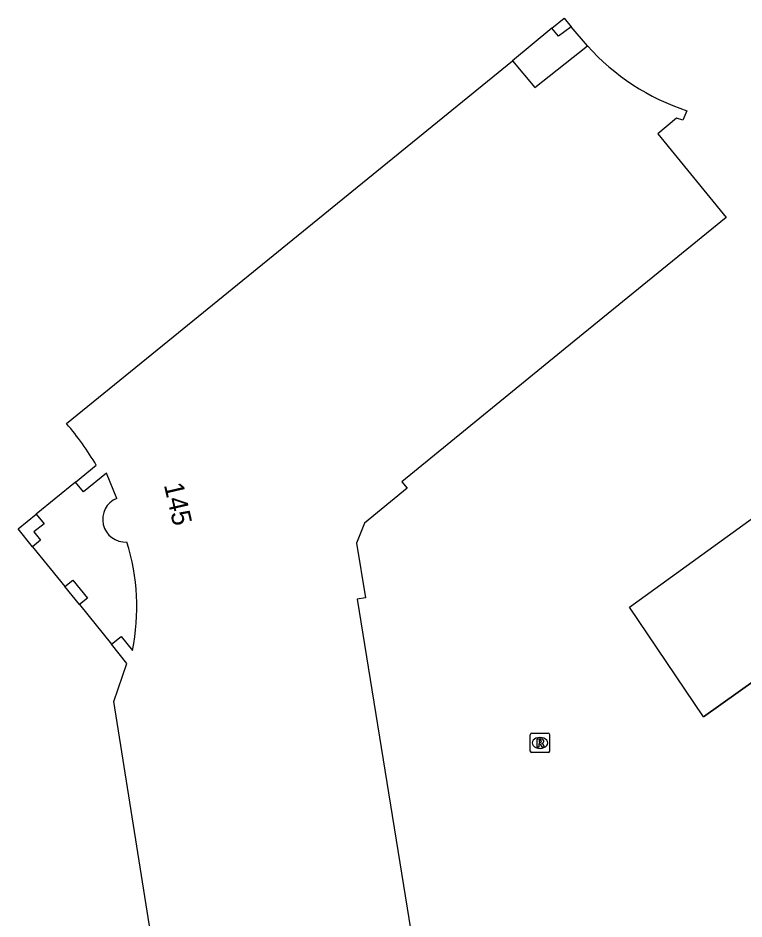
# Model space of a CAD drawing. Extents: x 159265 to 160143, y 383413 to 384319.
# Drawn here: x 159397.74 to 159435.22, y 383470.18 to 383516.69 of the extents above; entities that cross this region are included whole.
import ezdxf

# ---------------------------------------------------------------- set-up
doc = ezdxf.new("R2010")
doc.units = 0
for name, color, linetype in [('IMGEO_Muur', 7, 'Continuous'), ('IMGEO_Pand', 7, 'Continuous'), ('IMGEO_Pand_nummerreeks', 7, 'Continuous'), ('IMGEO_Pand_overbouw', 7, 'Continuous'), ('IMGEO_Rijbaan_lokaal_open', 7, 'Continuous'), ('IMGEO_Rioolput', 7, 'Continuous')]:
    doc.layers.add(name, color=color, linetype=linetype)

msp = doc.modelspace()

# ---------------------------------------------------------------- linework, layer by layer
at = {"layer": 'IMGEO_Muur'}
msp.add_lwpolyline([(159433.127, 383480.612), (159439.516, 383485.157)], dxfattribs=at)
at = {"layer": 'IMGEO_Pand'}
for points in [[(159426.287, 383516.236), (159425.636, 383515.758), (159425.297, 383516.165), (159425.927, 383516.689), (159426.287, 383516.236)], [(159400.246, 383495.751), (159405.469, 383500), (159423.274, 383514.484), (159424.425, 383513.1), (159427.133, 383515.255)], [(159432.269, 383511.904), (159432.066, 383511.417), (159431.728, 383511.517), (159430.765, 383510.719), (159434.287, 383506.395), (159426.452, 383500), (159417.555, 383492.739), (159417.824, 383492.42), (159415.617, 383490.613), (159415.218, 383489.58), (159415.684, 383486.763), (159415.255, 383486.697), (159418.019, 383469.567), (159418.569, 383466.16)], [(159402.838, 383491.894), (159402.311, 383493.198), (159401.115, 383492.226), (159400.703, 383492.732), (159401.781, 383493.603)], [(159398.487, 383489.399), (159397.739, 383490.322), (159398.671, 383491.079), (159399.081, 383490.575), (159398.561, 383490.167), (159398.907, 383489.739), (159398.487, 383489.399)], [(159400.91, 383486.407), (159400.155, 383487.339), (159400.575, 383487.68), (159401.33, 383486.747), (159400.91, 383486.407)], [(159409.695, 383449.207), (159407.956, 383460.026), (159407.41, 383463.425), (159405.588, 383463.126), (159402.681, 383481.403), (159403.364, 383483.376), (159402.564, 383484.363), (159403.07, 383484.772), (159403.655, 383484.049)]]:
    msp.add_lwpolyline(points, dxfattribs=at)
for centre, radius, start, end in [((159435.931, 383523.129), 11.807, 221.8255, 251.9294), ((159388.605, 383485.809), 15.309, 30.6036, 40.497), ((159403.283, 383490.81), 1.172, 112.3399, 273.8461), ((159392.466, 383486.266), 11.406, 348.7902, 17.2085)]:
    msp.add_arc(centre, radius, start, end, dxfattribs=at)
at = {"layer": 'IMGEO_Pand_overbouw'}
msp.add_lwpolyline([(159427.133, 383515.255), (159426.287, 383516.236), (159425.636, 383515.758), (159425.297, 383516.165), (159423.274, 383514.484), (159424.425, 383513.1)], close=True, dxfattribs=at)
for points in [[(159402.838, 383491.894), (159402.311, 383493.198), (159401.115, 383492.226), (159400.703, 383492.732), (159398.671, 383491.079), (159399.081, 383490.575), (159398.561, 383490.167), (159398.907, 383489.739), (159398.487, 383489.399), (159400.155, 383487.339), (159400.575, 383487.68), (159401.33, 383486.747), (159400.91, 383486.407), (159402.564, 383484.363)], [(159402.564, 383484.363), (159403.07, 383484.772), (159403.655, 383484.049)]]:
    msp.add_lwpolyline(points, dxfattribs=at)
for centre, radius, start, end in [((159403.283, 383490.81), 1.172, 112.3399, 273.8461), ((159392.466, 383486.266), 11.406, 348.7902, 17.2085)]:
    msp.add_arc(centre, radius, start, end, dxfattribs=at)
at = {"layer": 'IMGEO_Rijbaan_lokaal_open'}
msp.add_lwpolyline([(159439.516, 383485.157), (159433.127, 383480.612), (159429.309, 383486.278), (159448.278, 383500), (159458.947, 383507.895)], dxfattribs=at)
at = {"layer": 'IMGEO_Rioolput'}
for p, q in [((159424.258, 383479.77), (159425.11, 383479.77)), ((159424.183, 383478.844), (159424.183, 383479.696)), ((159424.671, 383479.55), (159424.696, 383479.55)), ((159425.184, 383479.696), (159425.184, 383478.844)), ((159424.694, 383478.99), (159424.669, 383478.99)), ((159425.11, 383478.77), (159424.258, 383478.77))]:
    msp.add_line(p, q, dxfattribs=at)
for points in [[(159424.258, 383479.77), (159425.11, 383479.77)], [(159424.183, 383478.844), (159424.183, 383479.696)], [(159424.772, 383479.468), (159424.52, 383479.47), (159424.52, 383479.07)], [(159424.698, 383479.389), (159424.644, 383479.389), (159424.644, 383479.308)], [(159424.644, 383479.308), (159424.696, 383479.308)], [(159425.184, 383479.696), (159425.184, 383478.844)], [(159424.52, 383479.07), (159424.644, 383479.07), (159424.644, 383479.232), (159424.655, 383479.232)], [(159424.702, 383479.203), (159424.773, 383479.07), (159424.913, 383479.07), (159424.848, 383479.196)], [(159425.11, 383478.77), (159424.258, 383478.77)]]:
    msp.add_lwpolyline(points, dxfattribs=at)
for centre, radius, start, end in [((159424.26, 383479.694), 0.0765, 91.552, 178.448), ((159424.26, 383479.694), 0.0765, 91.552, 178.448), ((159425.108, 383479.694), 0.0765, 1.552, 88.448), ((159425.108, 383479.694), 0.0765, 1.552, 88.448), ((159424.68, 383479.497), 0.19, 274.7715, 282.9687), ((159424.704, 383479.293), 0.0964, 77.0061, 93.1865), ((159424.718, 383479.35), 0.0378, 276.6634, 79.6772), ((159424.771, 383479.358), 0.109, 350.3612, 89.416), ((159424.769, 383479.358), 0.112, 277.5842, 350.9817), ((159424.26, 383478.846), 0.0765, 181.552, 268.448), ((159424.26, 383478.846), 0.0765, 181.552, 268.448), ((159424.654, 383479.179), 0.0533, 26.0293, 88.6989), ((159424.753, 383479.143), 0.108, 29.5134, 73.7905), ((159425.108, 383478.846), 0.0765, 271.552, 358.448), ((159425.108, 383478.846), 0.0765, 271.552, 358.448)]:
    msp.add_arc(centre, radius, start, end, dxfattribs=at)
for centre, major_axis, ratio, start_param, end_param in [((159424.67, 383479.27), (-0.387, 0.002), 0.722429, 4.712389, 7.853982), ((159424.695, 383479.27), (-0.39, 0.002), 0.717154, 1.570796, 4.712389)]:
    msp.add_ellipse(centre, major_axis=major_axis, ratio=ratio, start_param=start_param, end_param=end_param, dxfattribs=at)

# ---------------------------------------------------------------- texts
at = {"layer": 'IMGEO_Pand_nummerreeks'}
msp.add_text('145', height=1, rotation=283.093, dxfattribs=at).set_placement((159405.264, 383492.589))

doc.saveas('drawing.dxf')
